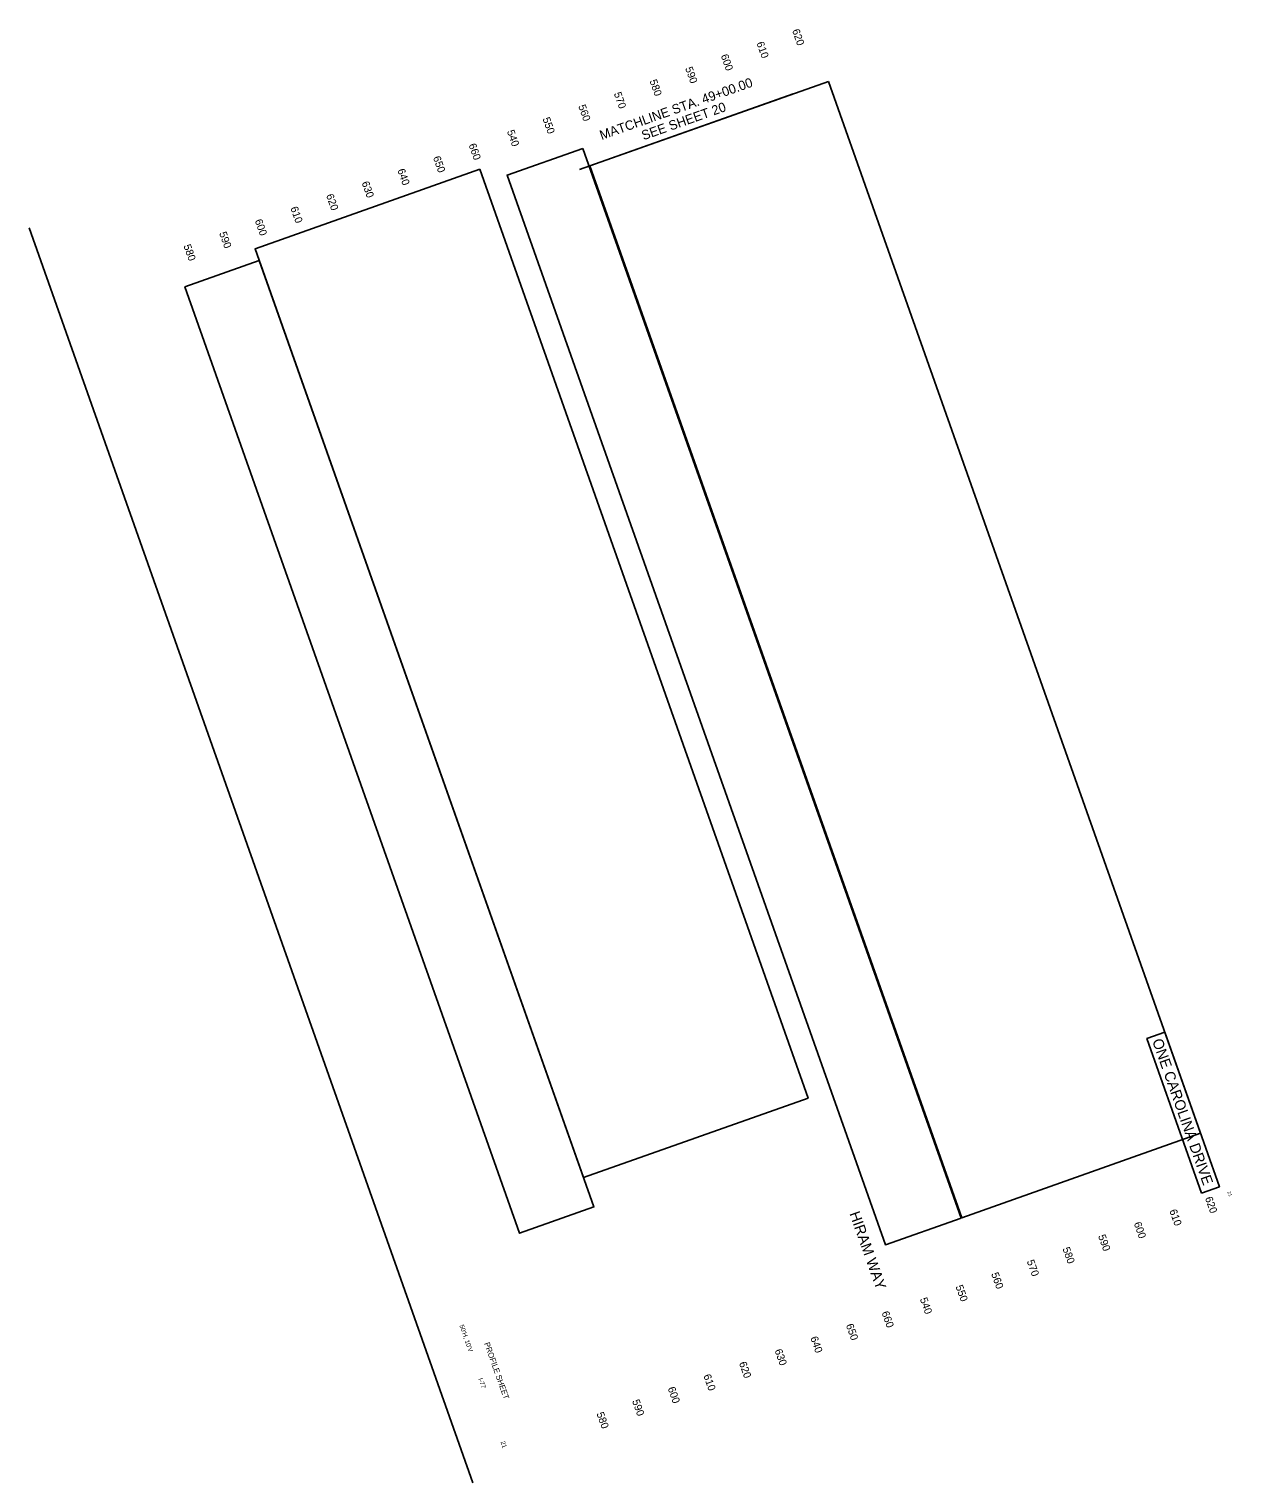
# Model space of a CAD drawing. Extents: x 1995702 to 1997293, y 1125807 to 1127729.
import ezdxf

# ---------------------------------------------------------------- set-up
doc = ezdxf.new("R2010")
doc.units = 0
for name, color, linetype in [('RD_DDB_ElevTX', 7, 'Continuous'), ('RD_DDB_Profile_Lbl', 7, 'Continuous'), ('RD_DDB_Profile_PR', 7, 'Continuous')]:
    doc.layers.add(name, color=color, linetype=linetype)

msp = doc.modelspace()

# ---------------------------------------------------------------- linework, layer by layer
at = {"layer": 'RD_DDB_ElevTX'}
msp.add_line((1995702.2, 1127466.5), (1996289.2, 1125807.3), dxfattribs=at)
msp.add_lwpolyline([(1997252.8, 1126190.5), (1997180.6, 1126394.7), (1997204.2, 1126403), (1997276.4, 1126198.8)], close=True, dxfattribs=at)
msp.add_lwpolyline([(1997252.8, 1126190.5), (1997180.6, 1126394.7), (1997204.2, 1126403), (1997276.4, 1126198.8)], close=True, dxfattribs=at)
at = {"layer": 'RD_DDB_Profile_Lbl'}
for points in [[(1996759.5, 1127660.1), (1997251.4, 1126269.5), (1996935.9, 1126157.9), (1996443.9, 1127548.5)], [(1996434.5, 1127571.6), (1996934.8, 1126157.5), (1996834.7, 1126122.1), (1996334.5, 1127536.3)], [(1996298.2, 1127544), (1996732.6, 1126316), (1996435.6, 1126210.9), (1996001.2, 1127438.9)], [(1996006.7, 1127423.3), (1996449.3, 1126172.1), (1996351, 1126137.3), (1995908.3, 1127388.5)]]:
    msp.add_lwpolyline(points, close=True, dxfattribs=at)
at = {"layer": 'RD_DDB_Profile_PR'}
msp.add_line((1996712.8, 1127643.6), (1996430, 1127543.5), dxfattribs=at)

# ---------------------------------------------------------------- texts
at = {"layer": 'RD_DDB_ElevTX'}
for s, height, p in [('620', 10, (1996711.2, 1127727.5)), ('600', 10, (1996616.9, 1127694.2)), ('610', 10, (1996664.1, 1127710.8)), ('590', 10, (1996569.8, 1127677.5)), ('580', 10, (1996522.7, 1127660.8)), ('570', 10, (1996475.5, 1127644.1)), ('560', 10, (1996428.4, 1127627.5)), ('550', 10, (1996381.2, 1127610.8)), ('540', 10, (1996334.1, 1127594.1)), ('650', 10, (1996236.3, 1127559.5)), ('660', 10, (1996283.4, 1127576.2)), ('640', 10, (1996189.2, 1127542.8)), ('630', 10, (1996142, 1127526.2)), ('620', 10, (1996094.9, 1127509.5)), ('610', 10, (1996047.7, 1127492.8)), ('600', 10, (1996000.6, 1127476.1)), ('580', 10, (1995906.3, 1127442.8)), ('590', 10, (1995953.5, 1127459.5)), ('ONE CAROLINA DRIVE', 14, (1997187.4, 1126391.8)), ('620', 10, (1997257.3, 1126183.8)), ('21', 4.5, (1997287, 1126192)), ('HIRAM WAY', 14, (1996787, 1126163.4)), ('610', 10, (1997210.2, 1126167.1)), ('600', 10, (1997163.1, 1126150.4)), ('580', 10, (1997068.8, 1126117.1)), ('590', 10, (1997115.9, 1126133.7)), ('570', 10, (1997021.6, 1126100.4)), ('560', 10, (1996974.5, 1126083.7)), ('550', 10, (1996927.4, 1126067)), ('540', 10, (1996880.2, 1126050.4)), ('660', 10, (1996829.6, 1126032.4)), ("50'H, 10'V", 6, (1996271.3, 1126015.3)), ('650', 10, (1996782.4, 1126015.8)), ('PROFILE SHEET', 7.5, (1996304, 1125991.7)), ('630', 10, (1996688.1, 1125982.4)), ('640', 10, (1996735.3, 1125999.1)), ('620', 10, (1996641, 1125965.7)), ('I-77', 6, (1996296.3, 1125944.8)), ('610', 10, (1996593.9, 1125949.1)), ('600', 10, (1996546.7, 1125932.4)), ('590', 10, (1996499.6, 1125915.7)), ('580', 10, (1996452.5, 1125899)), ('21', 6, (1996325.7, 1125861.4))]:
    msp.add_text(s, height=height, rotation=289.482, dxfattribs=at).set_placement(p)
at = {"layer": 'RD_DDB_Profile_PR'}
for s, p in [('MATCHLINE STA. 49+00.00', (1996459.5, 1127582.6)), ('SEE SHEET 20', (1996514.9, 1127582.3))]:
    msp.add_text(s, height=12.5, rotation=19.482, dxfattribs=at).set_placement(p)

doc.saveas('drawing.dxf')
